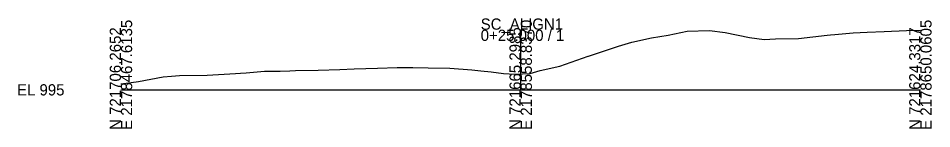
# Model space of a CAD drawing. Extents: x -2342 to 14913, y -10 to 5257.
# Drawn here: x -25.7 to 202.8, y 490.3 to 517.8 of the extents above; entities that cross this region are included whole.
import ezdxf

# ---------------------------------------------------------------- set-up
doc = ezdxf.new("R2010")
doc.units = 0
for name, color, linetype in [('Default', 7, 'Continuous'), ('GK_Cells', 7, 'Continuous'), ('SC_Scratch1', 7, 'Continuous'), ('XS_X_Ground_Line', 7, 'Continuous')]:
    doc.layers.add(name, color=color, linetype=linetype)

msp = doc.modelspace()

# ---------------------------------------------------------------- linework, layer by layer
at = {"layer": 'GK_Cells'}
for p, q in [((100, 500), (100, 515)), ((0, 500), (100, 500)), ((100, 500), (200, 500))]:
    msp.add_line(p, q, dxfattribs=at)
at = {"layer": 'SC_Scratch1'}
msp.add_lwpolyline([(0, 501.49), (0.01, 501.49), (4.37, 502.06), (10.55, 503.22), (12.63, 503.45), (14.64, 503.54), (21.59, 503.69), (28.68, 504.04), (29.91, 504.12), (31.34, 504.22), (35.9, 504.64), (39.87, 504.69), (42.24, 504.73), (43.67, 504.81), (49.35, 504.94), (54.77, 505.11), (58.37, 505.21), (64.18, 505.41), (69.12, 505.53), (72.99, 505.6), (76.85, 505.47), (82.25, 505.39), (87.77, 505), (90.05, 504.73), (92.59, 504.47), (95.74, 504.09), (98.54, 503.94), (102.4, 504.09), (104.89, 504.82), (109.78, 505.88), (116.88, 508.36), (117.01, 508.4), (117.22, 508.48), (124.47, 510.86), (127.84, 511.87), (132.71, 513.01), (136.89, 513.66), (141.62, 514.61), (147.24, 514.82), (151.2, 514.3), (157.24, 513.03), (160.92, 512.58), (163.77, 512.73), (169.47, 512.79), (176.65, 513.64), (177.51, 513.74), (178.62, 513.84), (183.21, 514.21), (186.7, 514.39), (190.94, 514.59), (196.49, 514.78), (200, 514.91)], dxfattribs=at)
at = {"layer": 'XS_X_Ground_Line'}
msp.add_lwpolyline([(0, 501.49), (0.01, 501.49), (4.37, 502.06), (10.55, 503.22), (12.63, 503.45), (14.64, 503.54), (21.59, 503.69), (28.68, 504.04), (29.91, 504.12), (31.34, 504.22), (35.9, 504.64), (39.87, 504.69), (42.24, 504.73), (43.67, 504.81), (49.35, 504.94), (54.77, 505.11), (58.37, 505.21), (64.18, 505.41), (69.12, 505.53), (72.99, 505.6), (76.85, 505.47), (82.25, 505.39), (87.77, 505), (90.05, 504.73), (92.59, 504.47), (95.74, 504.09), (98.54, 503.94), (102.4, 504.09), (104.89, 504.82), (109.78, 505.88), (116.88, 508.36), (117.01, 508.4), (117.22, 508.48), (124.47, 510.86), (127.84, 511.87), (132.71, 513.01), (136.89, 513.66), (141.62, 514.61), (147.24, 514.82), (151.2, 514.3), (157.24, 513.03), (160.92, 512.58), (163.77, 512.73), (169.47, 512.79), (176.65, 513.64), (177.51, 513.74), (178.62, 513.84), (183.21, 514.21), (186.7, 514.39), (190.94, 514.59), (196.49, 514.78), (200, 514.91)], dxfattribs=at)

# ---------------------------------------------------------------- texts
at = {"layer": 'Default'}
msp.add_text('-', height=0.0001, dxfattribs=at).set_placement((0, 500))
at = {"layer": 'GK_Cells'}
for s, p in [('E 2178467.6135', (2.8, 490)), ('E 2178558.8370', (102.8, 490)), ('E 2178650.0605', (202.8, 490)), ('N 721706.2652', (0, 490)), ('N 721665.2985', (100, 490)), ('N 721624.3317', (200, 490))]:
    msp.add_text(s, height=2.8, rotation=90, dxfattribs=at).set_placement(p)
for s, p in [('SC_ALIGN1', (90, 515)), ('0+25.000 / 1', (90, 512.2)), ('EL 995', (-26, 498.6))]:
    msp.add_text(s, height=2.8, dxfattribs=at).set_placement(p)
at = {"layer": 'SC_Scratch1'}
msp.add_text('X', height=0.0001, dxfattribs=at).set_placement((100, 504))

doc.saveas('drawing.dxf')
